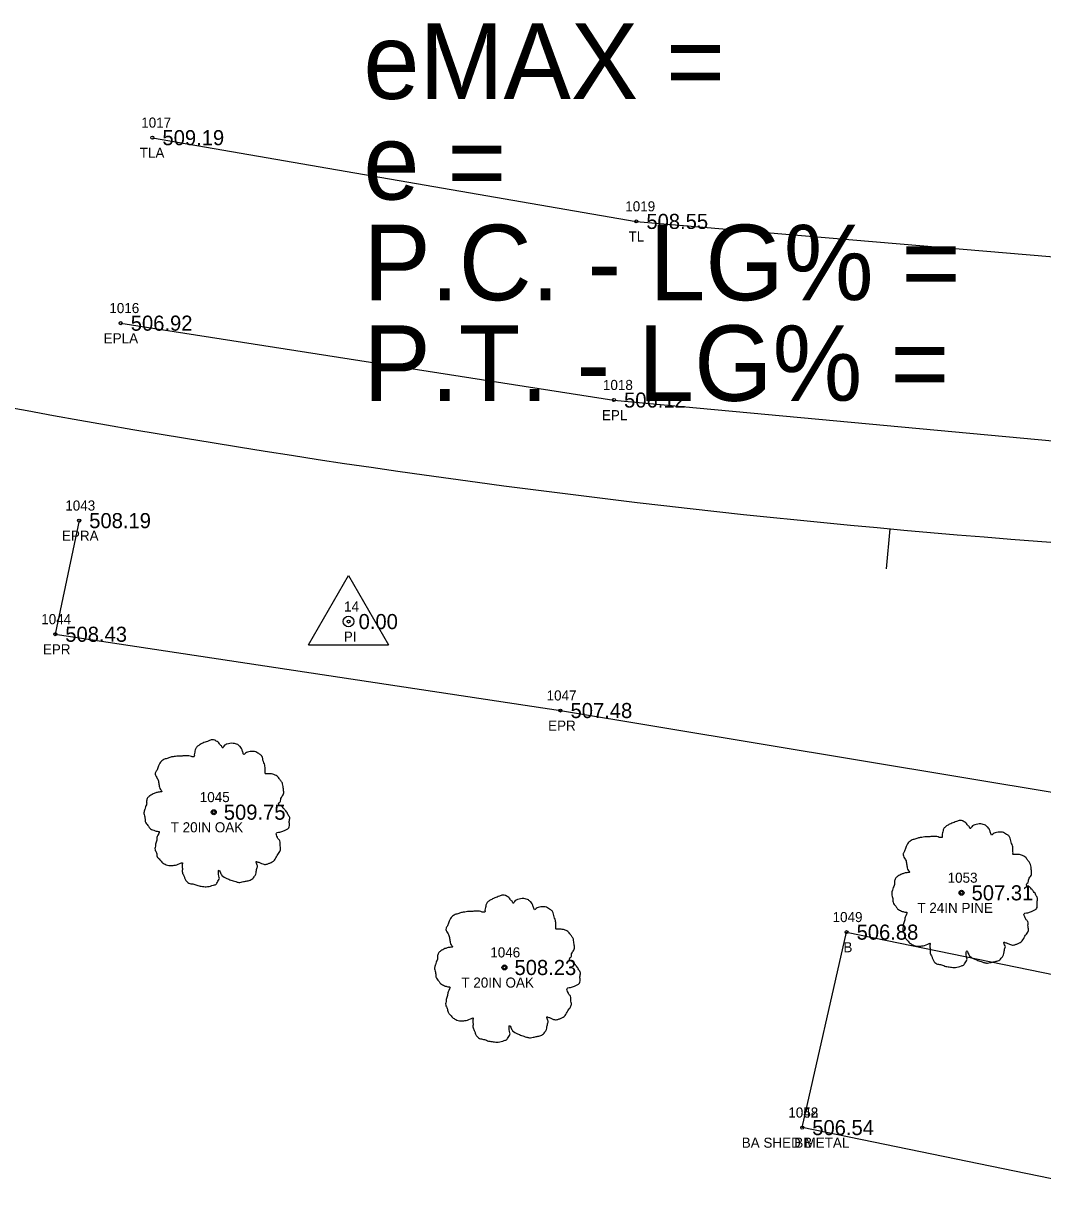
# Model space of a CAD drawing. Extents: x 1784103 to 1787401, y 770251 to 771298.
# Drawn here: x 1785074.2 to 1785175.5, y 770774 to 770890.5 of the extents above; entities that cross this region are included whole.
import ezdxf

# ---------------------------------------------------------------- set-up
doc = ezdxf.new("R2010")
doc.units = 0
for name, color, linetype in [('RD_EX_Bldg', 7, 'Continuous'), ('RD_EX_Bldg_txCode', 7, 'Continuous'), ('RD_EX_Road', 7, 'Continuous'), ('RD_EX_Road_txCode', 7, 'Continuous'), ('RD_EX_TX_Bldg_ELEV', 7, 'Continuous'), ('RD_EX_TX_Road_ELEV', 7, 'Continuous'), ('RD_EX_TX_VEG_ELEV', 7, 'Continuous'), ('RD_EX_VEG', 7, 'Continuous'), ('RD_EX_VEG_txCode', 7, 'Continuous'), ('RD_HC_Cl', 7, 'Continuous'), ('RD_HC_Data', 7, 'Continuous'), ('RD_HC_Data_Tic', 7, 'Continuous'), ('RD_HC_Survey_ELEV', 7, 'Continuous'), ('RD_HC_txCode', 7, 'Continuous'), ('RD_SMD_Locator', 7, 'Continuous')]:
    doc.layers.add(name, color=color, linetype=linetype)

msp = doc.modelspace()

# ---------------------------------------------------------------- linework, layer by layer
at = {"layer": 'RD_EX_Bldg'}
msp.add_lwpolyline([(1785151.62, 770780.79), (1785156.03, 770800.21), (1785188.51, 770793.55), (1785184.5, 770774.04), (1785151.62, 770780.79)], dxfattribs=at)
at = {"layer": 'RD_EX_Road'}
for points in [[(1785083.87, 770860.72), (1785132.91, 770853.08), (1785181.89, 770848.53), (1785200.96, 770847.97), (1785215.21, 770848.13), (1785231.38, 770846.18), (1785281.19, 770846.16), (1785330.68, 770847.27), (1785380.41, 770849.82), (1785480.96, 770852.71), (1785580.09, 770856.45), (1785680.2, 770859.84), (1785779.71, 770863.4)], [(1785079.74, 770841.1), (1785077.36, 770829.81), (1785127.59, 770822.23), (1785177.27, 770813.99), (1785180.45, 770828), (1785230.74, 770826.87), (1785281.16, 770827.18), (1785331.14, 770828.42), (1785381.03, 770830.27), (1785481.34, 770833.99), (1785580.1, 770837.94), (1785680.6, 770840.57), (1785780.28, 770843.87)]]:
    msp.add_lwpolyline(points, dxfattribs=at)
at = {"layer": 'RD_EX_VEG'}
msp.add_lwpolyline([(1785087.02, 770879.15), (1785135.13, 770870.83), (1785184.87, 770866.6), (1785186.65, 770884.02)], dxfattribs=at)
for centre, radius in [((1785093.12, 770812.13), 0.25), ((1785093.11, 770812.11), 0.0001), ((1785167.46, 770804.12), 0.25), ((1785167.45, 770804.1), 0.0001), ((1785122.02, 770796.7), 0.25), ((1785122.01, 770796.68), 0.0001)]:
    msp.add_circle(centre, radius, dxfattribs=at)
for points in [[(1785093.25, 770819.3), (1785092.95, 770819.32), (1785092.63, 770819.22), (1785092.38, 770819.12), (1785092.15, 770819.05), (1785091.93, 770818.95), (1785091.63, 770818.77), (1785091.4, 770818.57), (1785091.28, 770818.32), (1785091.23, 770818.1), (1785091.18, 770817.82), (1785091.18, 770817.65), (1785091.05, 770817.62), (1785090.9, 770817.65), (1785090.65, 770817.72), (1785090.4, 770817.72), (1785090.15, 770817.72), (1785089.8, 770817.7), (1785089.45, 770817.7), (1785089.18, 770817.65), (1785088.85, 770817.6), (1785088.48, 770817.47), (1785088.13, 770817.35), (1785087.83, 770817.1), (1785087.58, 770816.62), (1785087.45, 770816.27), (1785087.3, 770816.02), (1785087.45, 770815.57), (1785087.63, 770815.22), (1785087.65, 770815.02), (1785087.73, 770814.6), (1785087.83, 770814.37), (1785087.95, 770814.17), (1785087.88, 770814.15), (1785087.5, 770814.1), (1785087.2, 770814), (1785086.78, 770813.77), (1785086.55, 770813.55), (1785086.45, 770813.22), (1785086.43, 770812.87), (1785086.33, 770812.67), (1785086.26, 770812.4), (1785086.23, 770812.32), (1785086.18, 770812), (1785086.28, 770811.55), (1785086.31, 770811.2), (1785086.43, 770810.98), (1785086.58, 770810.8), (1785086.75, 770810.55), (1785087.15, 770810.33), (1785087.48, 770810.23), (1785087.68, 770810.2), (1785087.5, 770809.7), (1785087.45, 770809.35), (1785087.33, 770808.95), (1785087.33, 770808.88), (1785087.28, 770808.4), (1785087.43, 770808.08), (1785087.5, 770807.7), (1785087.68, 770807.48), (1785087.95, 770807.18), (1785088.28, 770806.95), (1785088.78, 770806.83), (1785089.18, 770806.85), (1785089.75, 770807.03), (1785090, 770807.1), (1785089.98, 770806.93), (1785090, 770806.55), (1785090, 770806.13), (1785090.15, 770805.8), (1785090.25, 770805.53), (1785090.4, 770805.28), (1785090.73, 770805.05), (1785091.13, 770804.98), (1785091.55, 770804.83), (1785092, 770804.75), (1785092.5, 770804.73), (1785093.1, 770804.88), (1785093.38, 770805), (1785093.48, 770805.18), (1785093.68, 770805.55), (1785093.63, 770805.78), (1785093.65, 770806.38), (1785093.75, 770806.2), (1785093.93, 770805.85), (1785094.43, 770805.55), (1785094.83, 770805.38), (1785095.3, 770805.23), (1785095.6, 770805.15), (1785096.08, 770805.23), (1785096.45, 770805.3), (1785096.83, 770805.43), (1785097.13, 770805.7), (1785097.3, 770805.98), (1785097.35, 770806.25), (1785097.43, 770806.63), (1785097.48, 770806.8)], [(1785097.48, 770806.8), (1785097.4, 770806.98), (1785097.35, 770807.23), (1785097.43, 770807.2), (1785097.6, 770807.15), (1785097.88, 770807.03), (1785098.1, 770806.95), (1785098.42, 770806.98), (1785098.7, 770807.08), (1785099.15, 770807.35), (1785099.42, 770807.83), (1785099.7, 770808.23), (1785099.77, 770808.55), (1785099.72, 770808.78), (1785099.7, 770809.28), (1785099.5, 770809.53), (1785099.45, 770809.65), (1785099.35, 770810.05), (1785099.42, 770810.1), (1785099.7, 770810.15), (1785100.07, 770810.28), (1785100.35, 770810.4), (1785100.57, 770810.58), (1785100.65, 770810.8), (1785100.62, 770811.2), (1785100.67, 770811.6), (1785100.6, 770811.75), (1785100.5, 770811.9), (1785100.42, 770812.1), (1785100.27, 770812.25), (1785100.17, 770812.4), (1785100.07, 770812.5), (1785099.95, 770812.65), (1785099.77, 770812.77), (1785099.62, 770812.82), (1785099.57, 770812.97), (1785099.72, 770813.17), (1785099.77, 770813.27), (1785099.8, 770813.5), (1785100.02, 770813.85), (1785100.07, 770814.25), (1785100.02, 770814.67), (1785099.97, 770814.95), (1785099.82, 770815.22), (1785099.62, 770815.47), (1785099.5, 770815.65), (1785099.32, 770815.77), (1785099, 770815.9), (1785098.75, 770815.95), (1785098.4, 770815.95), (1785098.2, 770816), (1785098.22, 770816.05), (1785098.22, 770816.2), (1785098.22, 770816.47), (1785098.15, 770816.92), (1785098, 770817.42), (1785098, 770817.45), (1785097.9, 770817.7), (1785097.68, 770817.9), (1785097.5, 770818), (1785097.3, 770818.12), (1785097.05, 770818.15), (1785096.75, 770818.15), (1785096.48, 770818.1), (1785096.28, 770818), (1785096.1, 770817.87), (1785096.03, 770818.02), (1785095.93, 770818.32), (1785095.88, 770818.47), (1785095.73, 770818.65), (1785095.5, 770818.85), (1785095.05, 770818.97), (1785094.43, 770818.9), (1785094.13, 770818.7), (1785093.98, 770818.52), (1785093.93, 770818.65), (1785093.73, 770818.85), (1785093.63, 770819.02), (1785093.45, 770819.15), (1785093.3, 770819.25), (1785093.2, 770819.3)], [(1785167.59, 770811.28), (1785167.3, 770811.31), (1785166.97, 770811.21), (1785166.72, 770811.11), (1785166.5, 770811.03), (1785166.27, 770810.93), (1785165.97, 770810.76), (1785165.75, 770810.56), (1785165.62, 770810.31), (1785165.57, 770810.08), (1785165.52, 770809.81), (1785165.52, 770809.63), (1785165.4, 770809.61), (1785165.25, 770809.63), (1785165, 770809.71), (1785164.75, 770809.71), (1785164.5, 770809.71), (1785164.15, 770809.68), (1785163.8, 770809.68), (1785163.52, 770809.63), (1785163.2, 770809.58), (1785162.82, 770809.46), (1785162.47, 770809.33), (1785162.17, 770809.08), (1785161.92, 770808.61), (1785161.8, 770808.26), (1785161.65, 770808.01), (1785161.8, 770807.56), (1785161.97, 770807.21), (1785162, 770807.01), (1785162.07, 770806.59), (1785162.17, 770806.36), (1785162.3, 770806.16), (1785162.22, 770806.14), (1785161.85, 770806.09), (1785161.55, 770805.99), (1785161.12, 770805.76), (1785160.9, 770805.54), (1785160.8, 770805.21), (1785160.77, 770804.86), (1785160.67, 770804.66), (1785160.6, 770804.39), (1785160.57, 770804.31), (1785160.52, 770803.99), (1785160.62, 770803.54), (1785160.65, 770803.19), (1785160.77, 770802.96), (1785160.92, 770802.79), (1785161.1, 770802.54), (1785161.5, 770802.31), (1785161.82, 770802.21), (1785162.02, 770802.19), (1785161.85, 770801.69), (1785161.8, 770801.34), (1785161.67, 770800.94), (1785161.67, 770800.86), (1785161.62, 770800.39), (1785161.77, 770800.06), (1785161.85, 770799.69), (1785162.02, 770799.46), (1785162.3, 770799.16), (1785162.62, 770798.94), (1785163.12, 770798.81), (1785163.52, 770798.84), (1785164.1, 770799.01), (1785164.35, 770799.09), (1785164.32, 770798.91), (1785164.35, 770798.54), (1785164.35, 770798.11), (1785164.5, 770797.79), (1785164.6, 770797.51), (1785164.75, 770797.26), (1785165.07, 770797.04), (1785165.47, 770796.96), (1785165.9, 770796.81), (1785166.35, 770796.74), (1785166.85, 770796.71), (1785167.45, 770796.86), (1785167.72, 770796.99), (1785167.82, 770797.16), (1785168.02, 770797.54), (1785167.97, 770797.76), (1785167.99, 770798.36), (1785168.09, 770798.19), (1785168.27, 770797.84), (1785168.77, 770797.54), (1785169.17, 770797.36), (1785169.64, 770797.21), (1785169.94, 770797.14), (1785170.42, 770797.21), (1785170.79, 770797.29), (1785171.17, 770797.41), (1785171.47, 770797.69), (1785171.64, 770797.96), (1785171.69, 770798.24), (1785171.77, 770798.61), (1785171.82, 770798.79)], [(1785171.82, 770798.79), (1785171.74, 770798.96), (1785171.69, 770799.21), (1785171.77, 770799.19), (1785171.94, 770799.14), (1785172.22, 770799.01), (1785172.44, 770798.94), (1785172.77, 770798.96), (1785173.04, 770799.06), (1785173.49, 770799.34), (1785173.77, 770799.81), (1785174.04, 770800.21), (1785174.12, 770800.54), (1785174.07, 770800.76), (1785174.04, 770801.26), (1785173.84, 770801.51), (1785173.79, 770801.64), (1785173.69, 770802.04), (1785173.77, 770802.09), (1785174.04, 770802.14), (1785174.42, 770802.26), (1785174.69, 770802.39), (1785174.92, 770802.56), (1785174.99, 770802.79), (1785174.97, 770803.19), (1785175.02, 770803.59), (1785174.94, 770803.74), (1785174.84, 770803.89), (1785174.77, 770804.09), (1785174.62, 770804.24), (1785174.52, 770804.39), (1785174.42, 770804.49), (1785174.29, 770804.64), (1785174.12, 770804.76), (1785173.97, 770804.81), (1785173.92, 770804.96), (1785174.07, 770805.16), (1785174.12, 770805.26), (1785174.14, 770805.49), (1785174.37, 770805.84), (1785174.42, 770806.24), (1785174.37, 770806.66), (1785174.32, 770806.94), (1785174.17, 770807.21), (1785173.97, 770807.46), (1785173.84, 770807.64), (1785173.67, 770807.76), (1785173.34, 770807.88), (1785173.09, 770807.93), (1785172.74, 770807.93), (1785172.54, 770807.98), (1785172.57, 770808.03), (1785172.57, 770808.18), (1785172.57, 770808.46), (1785172.49, 770808.91), (1785172.34, 770809.41), (1785172.34, 770809.43), (1785172.24, 770809.68), (1785172.02, 770809.88), (1785171.84, 770809.98), (1785171.64, 770810.11), (1785171.39, 770810.13), (1785171.09, 770810.13), (1785170.82, 770810.08), (1785170.62, 770809.98), (1785170.44, 770809.86), (1785170.37, 770810.01), (1785170.27, 770810.31), (1785170.22, 770810.46), (1785170.07, 770810.63), (1785169.84, 770810.83), (1785169.39, 770810.96), (1785168.77, 770810.88), (1785168.47, 770810.68), (1785168.32, 770810.51), (1785168.27, 770810.63), (1785168.07, 770810.83), (1785167.97, 770811.01), (1785167.79, 770811.13), (1785167.64, 770811.23), (1785167.54, 770811.28)], [(1785122.15, 770803.86), (1785121.85, 770803.89), (1785121.53, 770803.79), (1785121.28, 770803.69), (1785121.05, 770803.61), (1785120.83, 770803.51), (1785120.53, 770803.34), (1785120.3, 770803.14), (1785120.18, 770802.89), (1785120.13, 770802.66), (1785120.08, 770802.39), (1785120.08, 770802.21), (1785119.95, 770802.19), (1785119.8, 770802.21), (1785119.55, 770802.29), (1785119.3, 770802.29), (1785119.05, 770802.29), (1785118.7, 770802.26), (1785118.35, 770802.26), (1785118.08, 770802.21), (1785117.75, 770802.16), (1785117.38, 770802.04), (1785117.03, 770801.91), (1785116.73, 770801.66), (1785116.48, 770801.19), (1785116.36, 770800.84), (1785116.21, 770800.59), (1785116.36, 770800.14), (1785116.53, 770799.79), (1785116.56, 770799.59), (1785116.63, 770799.17), (1785116.73, 770798.94), (1785116.86, 770798.74), (1785116.78, 770798.72), (1785116.41, 770798.67), (1785116.11, 770798.57), (1785115.68, 770798.34), (1785115.46, 770798.12), (1785115.36, 770797.79), (1785115.33, 770797.44), (1785115.23, 770797.24), (1785115.16, 770796.97), (1785115.13, 770796.89), (1785115.08, 770796.57), (1785115.18, 770796.12), (1785115.21, 770795.77), (1785115.33, 770795.54), (1785115.48, 770795.37), (1785115.66, 770795.12), (1785116.06, 770794.89), (1785116.38, 770794.79), (1785116.58, 770794.77), (1785116.41, 770794.27), (1785116.36, 770793.92), (1785116.23, 770793.52), (1785116.23, 770793.44), (1785116.18, 770792.97), (1785116.33, 770792.64), (1785116.41, 770792.27), (1785116.58, 770792.04), (1785116.86, 770791.74), (1785117.18, 770791.52), (1785117.68, 770791.39), (1785118.08, 770791.42), (1785118.65, 770791.59), (1785118.9, 770791.67), (1785118.88, 770791.49), (1785118.9, 770791.12), (1785118.9, 770790.69), (1785119.05, 770790.37), (1785119.15, 770790.09), (1785119.3, 770789.84), (1785119.63, 770789.62), (1785120.03, 770789.54), (1785120.45, 770789.39), (1785120.9, 770789.32), (1785121.4, 770789.29), (1785122, 770789.44), (1785122.28, 770789.57), (1785122.38, 770789.74), (1785122.58, 770790.12), (1785122.53, 770790.34), (1785122.55, 770790.94), (1785122.65, 770790.77), (1785122.83, 770790.42), (1785123.33, 770790.12), (1785123.73, 770789.94), (1785124.2, 770789.79), (1785124.5, 770789.72), (1785124.98, 770789.79), (1785125.35, 770789.87), (1785125.73, 770789.99), (1785126.03, 770790.27), (1785126.2, 770790.54), (1785126.25, 770790.82), (1785126.33, 770791.19), (1785126.38, 770791.37)], [(1785126.38, 770791.37), (1785126.3, 770791.54), (1785126.25, 770791.79), (1785126.33, 770791.77), (1785126.5, 770791.72), (1785126.78, 770791.59), (1785127, 770791.52), (1785127.33, 770791.54), (1785127.6, 770791.64), (1785128.05, 770791.92), (1785128.33, 770792.39), (1785128.6, 770792.79), (1785128.67, 770793.12), (1785128.62, 770793.34), (1785128.6, 770793.84), (1785128.4, 770794.09), (1785128.35, 770794.22), (1785128.25, 770794.62), (1785128.33, 770794.67), (1785128.6, 770794.72), (1785128.97, 770794.84), (1785129.25, 770794.97), (1785129.47, 770795.14), (1785129.55, 770795.37), (1785129.52, 770795.77), (1785129.57, 770796.17), (1785129.5, 770796.32), (1785129.4, 770796.47), (1785129.32, 770796.67), (1785129.17, 770796.82), (1785129.07, 770796.97), (1785128.97, 770797.07), (1785128.85, 770797.22), (1785128.67, 770797.34), (1785128.53, 770797.39), (1785128.48, 770797.54), (1785128.62, 770797.74), (1785128.67, 770797.84), (1785128.7, 770798.07), (1785128.92, 770798.42), (1785128.97, 770798.82), (1785128.92, 770799.24), (1785128.87, 770799.51), (1785128.72, 770799.79), (1785128.53, 770800.04), (1785128.4, 770800.21), (1785128.23, 770800.34), (1785127.9, 770800.46), (1785127.65, 770800.51), (1785127.3, 770800.51), (1785127.1, 770800.56), (1785127.13, 770800.61), (1785127.13, 770800.76), (1785127.13, 770801.04), (1785127.05, 770801.49), (1785126.9, 770801.99), (1785126.9, 770802.01), (1785126.8, 770802.26), (1785126.58, 770802.46), (1785126.4, 770802.56), (1785126.2, 770802.69), (1785125.95, 770802.71), (1785125.65, 770802.71), (1785125.38, 770802.66), (1785125.18, 770802.56), (1785125, 770802.44), (1785124.93, 770802.59), (1785124.83, 770802.89), (1785124.78, 770803.04), (1785124.63, 770803.21), (1785124.4, 770803.41), (1785123.95, 770803.54), (1785123.33, 770803.46), (1785123.03, 770803.26), (1785122.88, 770803.09), (1785122.83, 770803.21), (1785122.63, 770803.41), (1785122.53, 770803.59), (1785122.35, 770803.71), (1785122.2, 770803.81), (1785122.1, 770803.86)]]:
    msp.add_spline(points, degree=3, dxfattribs=at)
at = {"layer": 'RD_HC_Cl'}
msp.add_arc((1785246.88, 771791.29), 954.93, 251.4323, 271.9359, dxfattribs=at)
at = {"layer": 'RD_HC_Data'}
for p, q in [((1785102.55, 770828.77), (1785106.53, 770835.65)), ((1785106.53, 770835.65), (1785110.49, 770828.77)), ((1785102.55, 770828.77), (1785110.49, 770828.77))]:
    msp.add_line(p, q, dxfattribs=at)
msp.add_circle((1785106.52, 770831.07), 0.529, dxfattribs=at)
at = {"layer": 'RD_HC_Data_Tic'}
msp.add_line((1785160.33, 770840.29), (1785159.97, 770836.3), dxfattribs=at)
at = {"layer": 'RD_SMD_Locator'}
for centre in [(1785087.02, 770879.15), (1785135.13, 770870.83), (1785083.87, 770860.72), (1785132.91, 770853.08), (1785079.74, 770841.1), (1785106.52, 770831.07), (1785077.36, 770829.81), (1785127.59, 770822.23), (1785093.12, 770812.13), (1785167.46, 770804.12), (1785156.03, 770800.21), (1785122.02, 770796.7), (1785151.62, 770780.79), (1785151.62, 770780.79)]:
    msp.add_circle(centre, 0.15, dxfattribs=at)

# ---------------------------------------------------------------- texts
at = {"layer": 'RD_EX_Bldg_txCode'}
for s, p in [('1049', (1785154.64, 770801.21)), ('B', (1785155.72, 770798.21)), ('1048', (1785150.24, 770781.79)), ('1052', (1785150.24, 770781.79)), ('BA SHED METAL', (1785145.61, 770778.79)), ('BB', (1785150.84, 770778.79))]:
    msp.add_text(s, height=1, dxfattribs=at).set_placement(p)
at = {"layer": 'RD_EX_Road_txCode'}
for s, p in [('1016', (1785082.74, 770861.72)), ('EPLA', (1785082.18, 770858.72)), ('1018', (1785131.81, 770854.08)), ('EPL', (1785131.71, 770851.08)), ('1043', (1785078.36, 770842.1)), ('EPRA', (1785078.03, 770839.1)), ('1044', (1785075.97, 770830.81)), ('EPR', (1785076.13, 770827.81)), ('1047', (1785126.21, 770823.23)), ('EPR', (1785126.36, 770820.23))]:
    msp.add_text(s, height=1, dxfattribs=at).set_placement(p)
at = {"layer": 'RD_EX_TX_Bldg_ELEV'}
for s, p in [('506.88', (1785157.03, 770799.46)), ('506.54', (1785152.62, 770780.04)), ('506.54', (1785152.62, 770780.04))]:
    msp.add_text(s, height=1.5, dxfattribs=at).set_placement(p)
at = {"layer": 'RD_EX_TX_Road_ELEV'}
for s, p in [('506.92', (1785084.87, 770859.97)), ('506.12', (1785133.91, 770852.33)), ('508.19', (1785080.74, 770840.35)), ('508.43', (1785078.36, 770829.06)), ('507.48', (1785128.59, 770821.48))]:
    msp.add_text(s, height=1.5, dxfattribs=at).set_placement(p)
at = {"layer": 'RD_EX_TX_VEG_ELEV'}
for s, p in [('509.19', (1785088.02, 770878.4)), ('508.55', (1785136.13, 770870.08)), ('509.75', (1785094.12, 770811.38)), ('507.31', (1785168.46, 770803.37)), ('508.23', (1785123.02, 770795.95))]:
    msp.add_text(s, height=1.5, dxfattribs=at).set_placement(p)
at = {"layer": 'RD_EX_VEG_txCode'}
for s, p in [('1017', (1785085.91, 770880.15)), ('TLA', (1785085.76, 770877.15)), ('1019', (1785134.03, 770871.83)), ('TL', (1785134.36, 770868.83)), ('1045', (1785091.73, 770813.13)), ('T 20IN OAK', (1785088.84, 770810.13)), ('1053', (1785166.08, 770805.12)), ('T 24IN PINE', (1785163.07, 770802.12)), ('1046', (1785120.61, 770797.7)), ('T 20IN OAK', (1785117.74, 770794.7))]:
    msp.add_text(s, height=1, dxfattribs=at).set_placement(p)
at = {"layer": 'RD_HC_Data'}
for s, p in [('eMAX = ', (1785108, 770883)), ('e = ', (1785108, 770873)), ('P.C. - LG% = ', (1785108, 770863)), ('P.T. - LG% = ', (1785108, 770853))]:
    msp.add_text(s, height=7.5, dxfattribs=at).set_placement(p)
at = {"layer": 'RD_HC_Survey_ELEV'}
msp.add_text('0.00', height=1.5, dxfattribs=at).set_placement((1785107.52, 770830.32))
at = {"layer": 'RD_HC_txCode'}
for s, p in [('14', (1785106.08, 770832.07)), ('PI', (1785106.05, 770829.07))]:
    msp.add_text(s, height=1, dxfattribs=at).set_placement(p)

doc.saveas('drawing.dxf')
